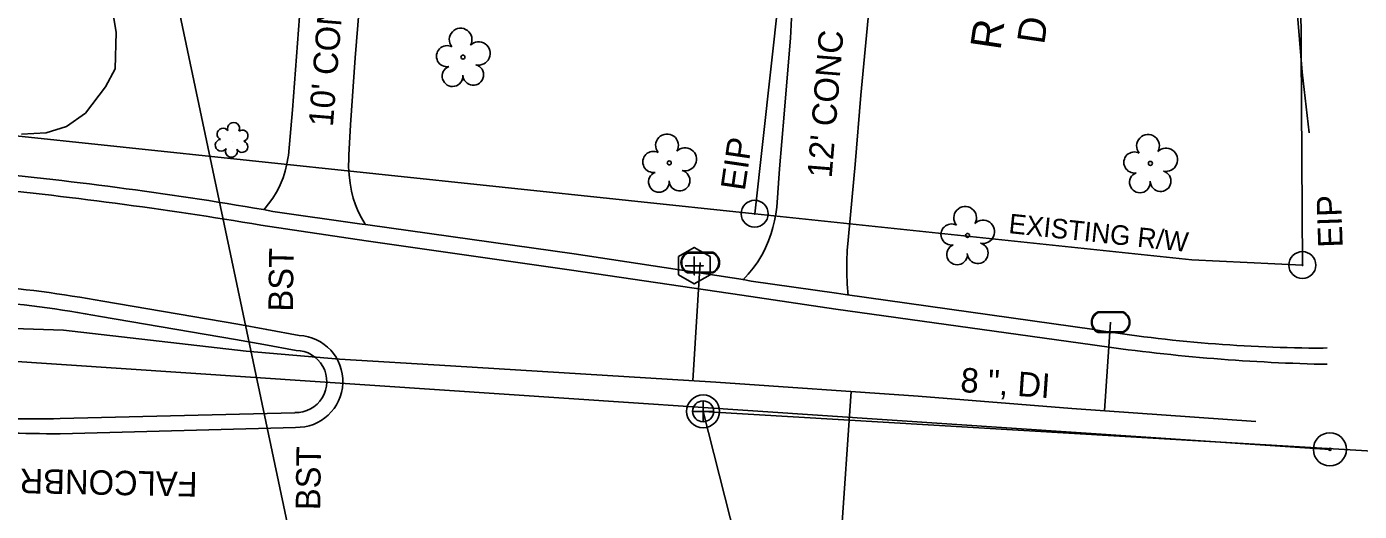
# Model space of a CAD drawing. Extents: x 1614611 to 1617571, y 898867 to 905462.
# Drawn here: x 1616119.3 to 1616337.3, y 904746.2 to 904825.6 of the extents above; entities that cross this region are included whole.
import ezdxf

# ---------------------------------------------------------------- set-up
doc = ezdxf.new("R2010")
doc.units = 0
for name, color, linetype in [('Exist Boundary Watershed Residential C 05', 7, 'Continuous'), ('Exist Drainage Structure Drop Inlet CELL', 7, 'Continuous'), ('Exist Horizontal Alignment Tick Label', 7, 'Continuous'), ('Exist Plan Preparation Watershed Yellow', 7, 'Continuous'), ('Exist Right of Way Line Text', 7, 'Continuous'), ('Exist Roads EOP Other Text', 7, 'Continuous'), ('Exist Roads EOP Text', 7, 'Continuous'), ('Exist Roads Soil', 7, 'Continuous'), ('Exist Survey Centerline Point CELL', 7, 'Continuous'), ('Exist Utilities Sanitary Sewer Manhole Leader', 7, 'Continuous'), ('Exist Utilities Sanitary Sewer UG Line', 7, 'Continuous'), ('Exist Utilities Water UG Line SUE LOS B', 7, 'Continuous'), ('Exist Utilities Water UG Line SUE LOS B Text', 7, 'Continuous'), ('Exist Vegetation Hedge Row', 7, 'Continuous'), ('Exist Vegetation Shrub CELL', 7, 'Continuous'), ('Exist Vegetation Tree CELL', 7, 'Continuous'), ('Old_Level_21', 7, 'Continuous'), ('Prop Drainage Structure Pipe Alternate 30in Label', 7, 'Continuous'), ('Prop Drainage Structure Pipe Removal', 7, 'Continuous'), ('Prop Drainage Structure Pipe Removal Label', 7, 'Continuous'), ('Prop Drainage Structure Pipe Stub Out CELL', 7, 'Continuous'), ('Prop Earthen Structure Head Ditch Label', 7, 'Continuous'), ('Prop SS Transition Line', 7, 'Continuous'), ('Raster_Level_2', 7, 'Continuous'), ('Scratch_Level_1', 7, 'Continuous'), ('Scratch_Level_9', 7, 'Continuous')]:
    doc.layers.add(name, color=color, linetype=linetype)

# ---------------------------------------------------------------- blocks, each defined once
blk = doc.blocks.new('EXIST UTILITIES SANITARY SEWER MANHOLE')
at = {"layer": 'Old_Level_21'}
blk.add_lwpolyline([(0, 0.03425), (0, -0.03425), (0, 0), (0.03425, 0), (-0.03425, 0)], dxfattribs=at)
for radius in [0.05389, 0.03425]:
    blk.add_circle((0, 0), radius, dxfattribs=at)
blk = doc.blocks.new('EXIST PROPERTY IRON PIN')
at = {"layer": 'Exist Plan Preparation Watershed Yellow'}
for radius in [0.0441, 0.00141]:
    blk.add_circle((0, 0), radius, dxfattribs=at)
blk = doc.blocks.new('EXIST SURVEY CENTERLINE POINT')
at = {"layer": 'Exist Survey Centerline Point CELL'}
for radius in [0.0542, 0.00375]:
    blk.add_circle((0, 0), radius, dxfattribs=at)
blk = doc.blocks.new('EXIST UTILITIES SANITARY SEWER CLEAN-OUT')
at = {"layer": 'Prop Drainage Structure Pipe Stub Out CELL'}
blk.add_line((0, 0), (0, 0), dxfattribs=at)
blk.add_lwpolyline([(-0.0516, 0.0299), (-0.0517, -0.0297), (-0.0001, -0.0596), (0.0516, -0.0299), (0.0517, 0.0297), (0.0001, 0.0596)], close=True, dxfattribs=at)
blk.add_lwpolyline([(0, 0.0302), (0, -0.0302), (0, 0), (0.0302, 0), (-0.0302, 0)], dxfattribs=at)
blk = doc.blocks.new('EXIST UTILITIES WATER METER')
at = {"layer": 'Prop SS Transition Line'}
blk.add_line((0, 0), (0, 0), dxfattribs=at)
for points in [[(-0.0408, 0.034), (0.0408, 0.034)], [(-0.0408, 0.0312), (0.0408, 0.0312)], [(0.0408, -0.0312), (-0.0413, -0.0312)], [(0.0408, -0.034), (-0.0413, -0.034)]]:
    blk.add_lwpolyline(points, dxfattribs=at)
for centre, radius, start, end in [((-0.0261, -0.0001), 0.0371, 113.178, 245.9794), ((-0.0259, -0.0001), 0.0347, 115.3009, 243.7824), ((0.0259, 0), 0.0371, 293.6483, 66.3084), ((0.0261, 0), 0.0345, 295.1272, 64.8728)]:
    blk.add_arc(centre, radius, start, end, dxfattribs=at)

msp = doc.modelspace()

# ---------------------------------------------------------------- linework, layer by layer
at = {"layer": 'Exist Boundary Watershed Residential C 05'}
for p, q in [((1616153.46, 904774.38), (1616131.33, 904778.15)), ((1616331.41, 904772.96), (1616332.06, 904773.02)), ((1616124.73, 904761.42), (1616163.14, 904762.39))]:
    msp.add_line(p, q, dxfattribs=at)
for points in [[(1616158.03, 904795.62), (1616159.56, 904795.34), (1616173.72, 904793.3), (1616175.09, 904793.15), (1616208.85, 904788.38), (1616236.52, 904784.21), (1616237.78, 904783.93), (1616251.78, 904781.95), (1616253.19, 904781.72), (1616293.9, 904775.98)], [(1616163.34, 904772.57), (1616158.06, 904773.54), (1616153.46, 904774.38)]]:
    msp.add_lwpolyline(points, dxfattribs=at)
for centre, major_axis, ratio, start_param, end_param in [((1616048.53, 904184.43), (-608.22, -151.1), 0.988965, 4.29574, 4.373231), ((1616099.18, 904603.95), (-79.17, 158.63), 0.997635, 5.636596, 5.750692), ((1616332.51, 905012.13), (-169.15, -169.6), 0.996995, 0.623431, 0.780954), ((1616163.3, 904767.48), (-0.3, -5.08), 0.997382, 0.027413, 3.192986), ((1616118.91, 904933.58), (153.29, -80.68), 0.992593, 5.125907, 5.227499)]:
    msp.add_ellipse(centre, major_axis=major_axis, ratio=ratio, start_param=start_param, end_param=end_param, dxfattribs=at)
at = {"layer": 'Exist Roads Soil'}
msp.add_lwpolyline([(1616329.11, 904808.17), (1616327.97, 904818.1), (1616327.3, 904826.14), (1616326.76, 904832.61), (1616326.49, 904838.61), (1616326.45, 904850.23), (1616326.36, 904863.62), (1616326.04, 904869.85), (1616325.49, 904876.93), (1616324.84, 904881.85), (1616324.53, 904886.27), (1616324.25, 904892.13), (1616324.34, 904899.56), (1616324.32, 904904.37), (1616324.15, 904906), (1616323.85, 904908.06), (1616323.42, 904909.71), (1616323.3, 904910.02)], dxfattribs=at)
at = {"layer": 'Exist Utilities Sanitary Sewer Manhole Leader'}
msp.add_lwpolyline([(1616229.94, 904762.61), (1616238.81, 904727.79), (1616238.63, 904714.56)], dxfattribs=at)
at = {"layer": 'Exist Utilities Sanitary Sewer UG Line'}
msp.add_line((1616229.94, 904762.61), (1616469.36, 904748.32), dxfattribs=at)
at = {"layer": 'Exist Utilities Water UG Line SUE LOS B'}
for p, q in [((1616229.47, 904786.96), (1616228.27, 904767.6)), ((1616296.62, 904777.2), (1616295.61, 904762.68)), ((1616254.18, 904765.85), (1616252.31, 904738.57))]:
    msp.add_line(p, q, dxfattribs=at)
msp.add_lwpolyline([(1616031.55, 904781.73), (1616048.33, 904780.7), (1616063.63, 904779.16), (1616086.73, 904777.45), (1616104.04, 904776.6), (1616125.28, 904775.88), (1616155.2, 904772.46), (1616170.46, 904771.15), (1616188.59, 904770.06), (1616232.05, 904767.36), (1616265.11, 904765.1), (1616290.28, 904763.06), (1616320.36, 904760.94)], dxfattribs=at)
at = {"layer": 'Exist Vegetation Hedge Row'}
msp.add_lwpolyline([(1616116.69, 904837.02), (1616122.39, 904837.13), (1616127.47, 904835.97), (1616131.39, 904832.89), (1616133.15, 904829.21), (1616133.89, 904824.68), (1616133.74, 904818.65), (1616132.16, 904815.74), (1616128.89, 904811.4), (1616125.76, 904809.23), (1616122.48, 904808.19), (1616118.43, 904807.96)], dxfattribs=at)
at = {"layer": 'Exist Vegetation Shrub CELL'}
msp.add_line((1616152.88, 904806.85), (1616152.88, 904806.85), dxfattribs=at)
for centre, radius, start, end in [((1616153.11, 904808.89), 0.99, 334.8391, 200.4717), ((1616151.08, 904806.15), 0.955, 95.1099, 327.9534), ((1616151.4, 904807.98), 0.968, 35.8908, 245.4216), ((1616154.52, 904805.92), 0.937, 204.9913, 73.4601), ((1616154.56, 904807.72), 0.929, 284.4567, 126.0861), ((1616152.76, 904805.17), 0.984, 151.2797, 21.387)]:
    msp.add_arc(centre, radius, start, end, dxfattribs=at)
at = {"layer": 'Exist Vegetation Tree CELL'}
for p, q in [((1616190.65, 904820.58), (1616190.65, 904820.58)), ((1616224.41, 904803.27), (1616224.41, 904803.27)), ((1616303.12, 904803.19), (1616303.12, 904803.19)), ((1616273.2, 904791.4), (1616273.2, 904791.4))]:
    msp.add_line(p, q, dxfattribs=at)
for centre in [(1616190.65, 904820.58), (1616224.41, 904803.27), (1616303.12, 904803.19), (1616273.2, 904791.4)]:
    msp.add_circle(centre, 0.326, dxfattribs=at)
for centre, radius, start, end in [((1616190.27, 904823.45), 1.86, 330.1651, 219.7134), ((1616188.05, 904820.73), 1.73, 62.6636, 279.3457), ((1616193.2, 904821.17), 1.9, 257.1011, 134.1999), ((1616188.95, 904817.46), 1.69, 111.5671, 6.231), ((1616192.33, 904817.68), 1.7, 181.2822, 74.56), ((1616224.03, 904806.14), 1.86, 330.1651, 219.7134), ((1616302.73, 904806.06), 1.86, 330.1651, 219.7134), ((1616221.81, 904803.43), 1.73, 62.6636, 279.3457), ((1616226.96, 904803.86), 1.9, 257.1011, 134.1999), ((1616300.51, 904803.34), 1.73, 62.6636, 279.3457), ((1616305.67, 904803.78), 1.9, 257.1011, 134.1999), ((1616222.71, 904800.15), 1.69, 111.5671, 6.231), ((1616226.08, 904800.37), 1.7, 181.2822, 74.56), ((1616301.41, 904800.07), 1.69, 111.5671, 6.231), ((1616304.79, 904800.29), 1.7, 181.2822, 74.56), ((1616272.81, 904794.27), 1.86, 330.1651, 219.7134), ((1616275.74, 904791.99), 1.9, 257.1011, 134.1999), ((1616270.59, 904791.55), 1.73, 62.6636, 279.3457), ((1616271.49, 904788.28), 1.69, 111.5671, 6.231), ((1616274.87, 904788.5), 1.7, 181.2822, 74.56)]:
    msp.add_arc(centre, radius, start, end, dxfattribs=at)
at = {"layer": 'Prop Drainage Structure Pipe Alternate 30in Label'}
for p, q in [((1616327.08, 904961.36), (1616327.99, 904786.54)), ((1616238.41, 904794.93), (1616252.88, 904926.93))]:
    msp.add_line(p, q, dxfattribs=at)
at = {"layer": 'Prop Earthen Structure Head Ditch Label'}
for p, q in [((1616010.65, 905462.23), (1616993.32, 900797.76)), ((1616238.41, 904794.93), (1616060.11, 904813.72)), ((1616309.91, 904787.4), (1616238.41, 904794.93)), ((1616327.99, 904786.54), (1616309.91, 904787.4))]:
    msp.add_line(p, q, dxfattribs=at)
at = {"layer": 'Raster_Level_2'}
msp.add_line((1616069.91, 904773.98), (1616332.49, 904756.39), dxfattribs=at)
at = {"layer": 'Scratch_Level_1'}
for points in [[(1616174.64, 904793.25), (1616174.05, 904794.26), (1616173.53, 904795.3), (1616173.08, 904796.38), (1616172.7, 904797.49), (1616172.4, 904798.62), (1616172.4, 904798.63), (1616172.17, 904799.96), (1616172.02, 904801.3), (1616171.95, 904802.65), (1616171.96, 904803.99), (1616171.98, 904804.55), (1616172.24, 904809.51), (1616173.03, 904820.46), (1616173.9, 904831.19), (1616174.63, 904841.51), (1616174.99, 904846), (1616175.25, 904849.13)], [(1616253.66, 904781.59), (1616253.51, 904783.44), (1616253.44, 904785.3), (1616253.44, 904787.15), (1616253.52, 904789), (1616253.6, 904790.02), (1616254.04, 904794.77), (1616254.8, 904803), (1616255.72, 904814.37), (1616257.17, 904829.3), (1616257.67, 904835.69), (1616257.93, 904838.89)], [(1616236.42, 904784.09), (1616237.3, 904785.04), (1616238.12, 904786.05), (1616238.87, 904787.1), (1616239.56, 904788.19), (1616239.58, 904788.22), (1616240.15, 904789.36), (1616240.64, 904790.52), (1616241.06, 904791.71), (1616241.33, 904792.67), (1616241.62, 904793.77), (1616241.84, 904794.89), (1616241.98, 904796.02), (1616241.98, 904796.03), (1616242.46, 904802.28), (1616243.19, 904811.22), (1616243.85, 904819.18), (1616244.23, 904823.67), (1616244.49, 904829.14)], [(1616158.13, 904795.66), (1616158.86, 904796.55), (1616159.53, 904797.49), (1616160.14, 904798.47), (1616160.67, 904799.49), (1616160.77, 904799.7), (1616161.21, 904800.81), (1616161.57, 904801.94), (1616161.85, 904803.09), (1616162.06, 904804.25), (1616162.09, 904804.46), (1616162.74, 904811.96), (1616163.9, 904827.23)]]:
    msp.add_lwpolyline(points, dxfattribs=at)
at = {"layer": 'Scratch_Level_9'}
for p, q in [((1616153.83, 904776.87), (1616131.73, 904780.63)), ((1616331.12, 904770.33), (1616332.06, 904770.31)), ((1616124.76, 904758.94), (1616163.24, 904759.98))]:
    msp.add_line(p, q, dxfattribs=at)
for points in [[(1616157.57, 904793.07), (1616174.81, 904790.54), (1616208.42, 904785.7), (1616236.25, 904781.64), (1616251.68, 904779.31), (1616293.65, 904773.48)], [(1616163.83, 904775.03), (1616158.54, 904776), (1616153.83, 904776.87)]]:
    msp.add_lwpolyline(points, dxfattribs=at)
for centre, major_axis, ratio, start_param, end_param in [((1616045.82, 904162.99), (-616.84, -186.32), 0.991347, 4.247013, 4.321869), ((1616094.34, 904581.4), (-182.71, -89.43), 0.994558, 4.074285, 4.174348), ((1616163.48, 904767.51), (-0.43, -7.52), 0.997058, 0.02653, 3.151433), ((1616339.4, 905084.68), (-201.09, -242.15), 0.997545, 0.548135, 0.667871), ((1616123.02, 905003.54), (209.75, -128.44), 0.992453, 5.192289, 5.265551)]:
    msp.add_ellipse(centre, major_axis=major_axis, ratio=ratio, start_param=start_param, end_param=end_param, dxfattribs=at)

# ---------------------------------------------------------------- block references
at = {"layer": 'Exist Horizontal Alignment Tick Label', "xscale": 50, "yscale": 50, "rotation": 1.7967031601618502e-12}
msp.add_blockref('EXIST SURVEY CENTERLINE POINT', (1616332.49, 904756.39), dxfattribs=at)
at = {"layer": 'Exist Plan Preparation Watershed Yellow', "xscale": 50, "yscale": 50}
for p in [(1616238.38, 904794.94), (1616327.99, 904786.54)]:
    msp.add_blockref('EXIST PROPERTY IRON PIN', p, dxfattribs=at)
at = {"layer": 'Old_Level_21', "xscale": 50, "yscale": 50}
msp.add_blockref('EXIST UTILITIES SANITARY SEWER MANHOLE', (1616229.94, 904762.61), dxfattribs=at)
at = {"layer": 'Prop Drainage Structure Pipe Stub Out CELL', "xscale": 50, "yscale": 50}
msp.add_blockref('EXIST UTILITIES SANITARY SEWER CLEAN-OUT', (1616228.49, 904786.45), dxfattribs=at)
at = {"layer": 'Prop SS Transition Line', "xscale": 50, "yscale": 50}
for p in [(1616229.47, 904786.96), (1616296.62, 904777.2)]:
    msp.add_blockref('EXIST UTILITIES WATER METER', p, dxfattribs=at)

# ---------------------------------------------------------------- texts
at = {"layer": 'Exist Drainage Structure Drop Inlet CELL'}
for rotation, p in [(81.6333, (1616236.75, 904798.59)), (91.9702, (1616334.59, 904789.47))]:
    msp.add_text('EIP', height=4, rotation=rotation, dxfattribs=at).set_placement(p)
at = {"layer": 'Exist Right of Way Line Text'}
msp.add_text('EXISTING R/W', height=3.2, rotation=353.9863, dxfattribs=at).set_placement((1616279.83, 904791.79))
at = {"layer": 'Exist Roads EOP Other Text'}
for s, rotation, p in [("10' CONC", 85.3602, (1616169.36, 904809.09)), ("12' CONC", 85.3675, (1616250.97, 904800.71))]:
    msp.add_text(s, height=4, rotation=rotation, dxfattribs=at).set_placement(p)
at = {"layer": 'Exist Roads EOP Text'}
for s, rotation, p in [('BST', 89.2167, (1616162.81, 904778.92)), ('BST', 89.2167, (1616167.28, 904746.42)), ('FALCONBRIDGE RD.', 178.8847, (1616147.27, 904752.65))]:
    msp.add_text(s, height=4, rotation=rotation, dxfattribs=at).set_placement(p)
at = {"layer": 'Exist Utilities Water UG Line SUE LOS B Text'}
msp.add_text('8 ", DI', height=4, rotation=355.9848, dxfattribs=at).set_placement((1616271.95, 904765.79))
at = {"layer": 'Prop Drainage Structure Pipe Removal'}
msp.add_text('RICKY PLUNKETT', height=5, rotation=81.6333, dxfattribs=at).set_placement((1616278.57, 904821.6))
at = {"layer": 'Prop Drainage Structure Pipe Removal Label'}
msp.add_text('DB 1359 PG 1274', height=4.5, rotation=81.6333, dxfattribs=at).set_placement((1616285.74, 904822.55))

doc.saveas('drawing.dxf')
